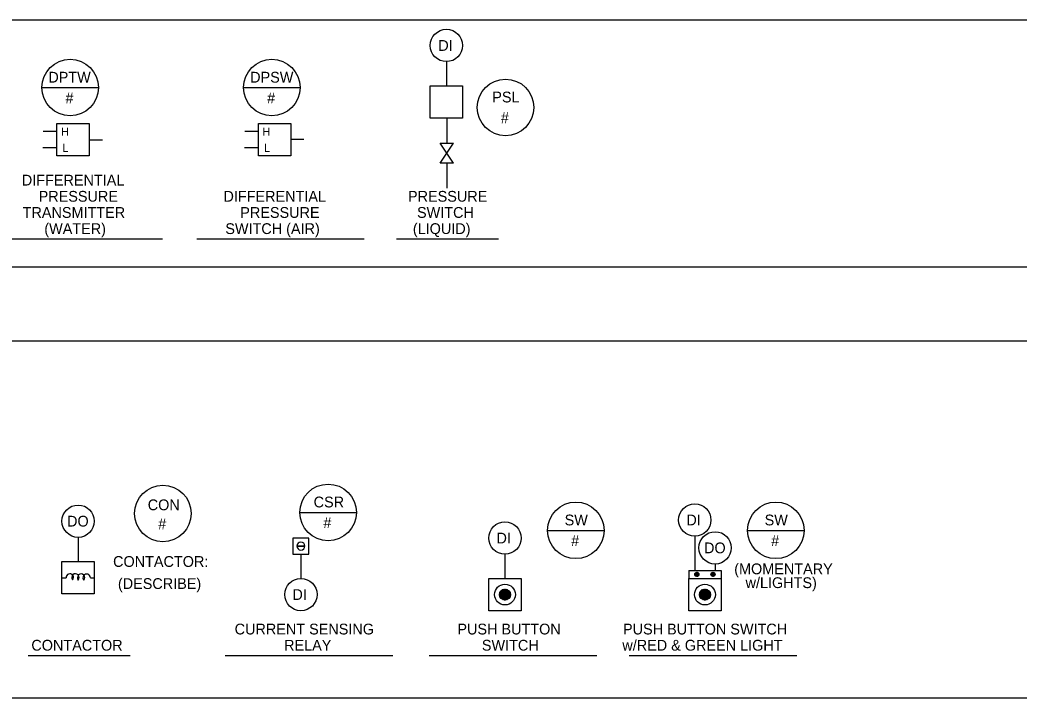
# Model space of a CAD drawing. Extents: x 10015 to 10283, y 10002 to 10184.
# Drawn here: x 10065.3 to 10127.1, y 10089.9 to 10131.8 of the extents above; entities that cross this region are included whole.
import ezdxf

# ---------------------------------------------------------------- set-up
doc = ezdxf.new("R2010")
doc.units = 0
for name, color, linetype in [('G-ANNO-TEXT', 7, 'Continuous'), ('G-DETL-LINE', 7, 'Continuous'), ('G-DETL-TEXT', 7, 'Continuous'), ('M-ANNO-NPLT', 7, 'Continuous')]:
    doc.layers.add(name, color=color, linetype=linetype)

msp = doc.modelspace()

# ---------------------------------------------------------------- linework, layer by layer
at = {"layer": 'G-ANNO-TEXT'}
for p, q in [((10063.729, 10118.291), (10074.097, 10118.291)), ((10076.201, 10118.291), (10086.569, 10118.291)), ((10088.558, 10118.291), (10094.87, 10118.291)), ((10065.778, 10092.522), (10072.09, 10092.522)), ((10077.965, 10092.522), (10088.333, 10092.522)), ((10090.586, 10092.522), (10100.955, 10092.522)), ((10102.957, 10092.522), (10113.325, 10092.522)), ((10102.957, 10092.522), (10113.325, 10092.522))]:
    msp.add_line(p, q, dxfattribs=at)
at = {"layer": 'G-DETL-LINE'}
for p, q in [((10091.647, 10129.256), (10091.647, 10127.76)), ((10090.647, 10127.76), (10092.647, 10127.76)), ((10090.647, 10125.76), (10090.647, 10127.76)), ((10092.647, 10127.76), (10092.647, 10125.76)), ((10067.561, 10123.427), (10067.561, 10125.427)), ((10067.561, 10125.427), (10069.561, 10125.427)), ((10069.561, 10125.427), (10069.561, 10123.427)), ((10080.033, 10123.427), (10080.033, 10125.427)), ((10080.033, 10125.427), (10082.033, 10125.427)), ((10082.033, 10125.427), (10082.033, 10123.427)), ((10092.647, 10125.76), (10090.647, 10125.76)), ((10091.672, 10125.775), (10091.672, 10124.213)), ((10067.561, 10124.927), (10066.714, 10124.927)), ((10080.033, 10124.927), (10079.186, 10124.927)), ((10069.561, 10124.427), (10070.377, 10124.427)), ((10082.012, 10124.464), (10082.827, 10124.464)), ((10091.261, 10122.977), (10092.084, 10124.213)), ((10091.261, 10124.213), (10092.084, 10124.213)), ((10092.084, 10122.977), (10091.261, 10124.213)), ((10067.561, 10123.927), (10066.684, 10123.927)), ((10080.033, 10123.927), (10079.156, 10123.927)), ((10069.561, 10123.427), (10067.561, 10123.427)), ((10082.033, 10123.427), (10080.033, 10123.427)), ((10092.084, 10122.977), (10091.261, 10122.977)), ((10091.672, 10122.992), (10091.672, 10121.43)), ((10068.867, 10099.83), (10068.867, 10098.334)), ((10083.147, 10099.789), (10082.147, 10099.789)), ((10082.147, 10099.789), (10082.147, 10098.789)), ((10083.147, 10098.789), (10083.147, 10099.789)), ((10107.012, 10099.903), (10107.012, 10097.789)), ((10082.147, 10098.789), (10083.147, 10098.789)), ((10082.647, 10099.289), (10082.397, 10099.289)), ((10082.397, 10099.289), (10082.647, 10099.289)), ((10082.897, 10099.289), (10082.647, 10099.289)), ((10082.647, 10099.289), (10082.897, 10099.289)), ((10082.647, 10098.789), (10082.647, 10097.289)), ((10095.269, 10098.786), (10095.269, 10097.289)), ((10067.867, 10098.334), (10069.867, 10098.334)), ((10067.867, 10096.334), (10067.867, 10098.334)), ((10069.867, 10098.334), (10069.867, 10096.334)), ((10108.266, 10098.178), (10108.266, 10097.789)), ((10106.639, 10097.789), (10106.639, 10097.289)), ((10107.013, 10097.537), (10107.142, 10097.666)), ((10107.013, 10097.537), (10107.142, 10097.666)), ((10107.013, 10097.549), (10107.149, 10097.413)), ((10107.013, 10097.549), (10107.149, 10097.413)), ((10107.013, 10097.526), (10107.127, 10097.413)), ((10107.013, 10097.526), (10107.127, 10097.413)), ((10107.014, 10097.517), (10107.162, 10097.664)), ((10107.014, 10097.561), (10107.118, 10097.664)), ((10107.014, 10097.517), (10107.162, 10097.664)), ((10107.014, 10097.561), (10107.118, 10097.664)), ((10107.016, 10097.568), (10107.168, 10097.416)), ((10107.016, 10097.568), (10107.168, 10097.416)), ((10107.019, 10097.499), (10107.18, 10097.66)), ((10107.019, 10097.499), (10107.18, 10097.66)), ((10107.021, 10097.585), (10107.185, 10097.421)), ((10107.021, 10097.585), (10107.185, 10097.421)), ((10107.024, 10097.593), (10107.086, 10097.654)), ((10107.024, 10097.593), (10107.086, 10097.654)), ((10107.025, 10097.484), (10107.195, 10097.653)), ((10107.025, 10097.484), (10107.195, 10097.653)), ((10107.028, 10097.6), (10107.2, 10097.428)), ((10107.028, 10097.6), (10107.2, 10097.428)), ((10107.033, 10097.469), (10107.209, 10097.645)), ((10107.033, 10097.469), (10107.209, 10097.645)), ((10107.036, 10097.614), (10107.214, 10097.436)), ((10107.036, 10097.614), (10107.214, 10097.436)), ((10107.043, 10097.457), (10107.222, 10097.636)), ((10107.043, 10097.457), (10107.222, 10097.636)), ((10107.046, 10097.626), (10107.226, 10097.446)), ((10107.046, 10097.626), (10107.226, 10097.446)), ((10107.054, 10097.446), (10107.233, 10097.625)), ((10107.054, 10097.446), (10107.233, 10097.625)), ((10107.058, 10097.636), (10107.237, 10097.457)), ((10107.058, 10097.636), (10107.237, 10097.457)), ((10107.066, 10097.436), (10107.243, 10097.613)), ((10107.066, 10097.436), (10107.243, 10097.613)), ((10107.07, 10097.646), (10107.246, 10097.47)), ((10107.07, 10097.646), (10107.246, 10097.47)), ((10107.08, 10097.427), (10107.252, 10097.599)), ((10107.08, 10097.427), (10107.252, 10097.599)), ((10107.085, 10097.654), (10107.254, 10097.484)), ((10107.085, 10097.654), (10107.254, 10097.484)), ((10107.095, 10097.42), (10107.258, 10097.584)), ((10107.095, 10097.42), (10107.258, 10097.584)), ((10107.1, 10097.66), (10107.26, 10097.5)), ((10107.1, 10097.66), (10107.26, 10097.5)), ((10107.112, 10097.415), (10107.263, 10097.567)), ((10107.112, 10097.415), (10107.263, 10097.567)), ((10107.118, 10097.664), (10107.265, 10097.518)), ((10107.118, 10097.664), (10107.265, 10097.518)), ((10107.131, 10097.413), (10107.266, 10097.548)), ((10107.131, 10097.413), (10107.266, 10097.548)), ((10107.138, 10097.666), (10107.266, 10097.538)), ((10107.138, 10097.666), (10107.266, 10097.538)), ((10107.154, 10097.413), (10107.266, 10097.525)), ((10107.154, 10097.413), (10107.266, 10097.525)), ((10107.163, 10097.664), (10107.264, 10097.562)), ((10107.163, 10097.664), (10107.264, 10097.562)), ((10107.196, 10097.653), (10107.253, 10097.595)), ((10107.196, 10097.653), (10107.253, 10097.595)), ((10108.141, 10097.666), (10108.012, 10097.538)), ((10108.141, 10097.666), (10108.012, 10097.538)), ((10108.148, 10097.413), (10108.013, 10097.548)), ((10108.148, 10097.413), (10108.013, 10097.548)), ((10108.125, 10097.413), (10108.013, 10097.525)), ((10108.125, 10097.413), (10108.013, 10097.525)), ((10108.161, 10097.664), (10108.014, 10097.518)), ((10108.161, 10097.664), (10108.014, 10097.518)), ((10108.116, 10097.664), (10108.015, 10097.562)), ((10108.116, 10097.664), (10108.015, 10097.562)), ((10108.167, 10097.415), (10108.016, 10097.567)), ((10108.167, 10097.415), (10108.016, 10097.567)), ((10108.179, 10097.66), (10108.019, 10097.5)), ((10108.179, 10097.66), (10108.019, 10097.5)), ((10108.184, 10097.42), (10108.021, 10097.584)), ((10108.184, 10097.42), (10108.021, 10097.584)), ((10108.194, 10097.654), (10108.025, 10097.484)), ((10108.194, 10097.654), (10108.025, 10097.484)), ((10108.083, 10097.653), (10108.026, 10097.595)), ((10108.083, 10097.653), (10108.026, 10097.595)), ((10108.199, 10097.427), (10108.027, 10097.599)), ((10108.199, 10097.427), (10108.027, 10097.599)), ((10108.209, 10097.646), (10108.033, 10097.47)), ((10108.209, 10097.646), (10108.033, 10097.47)), ((10108.213, 10097.436), (10108.036, 10097.613)), ((10108.213, 10097.436), (10108.036, 10097.613)), ((10108.221, 10097.636), (10108.042, 10097.457)), ((10108.221, 10097.636), (10108.042, 10097.457)), ((10108.225, 10097.446), (10108.046, 10097.625)), ((10108.225, 10097.446), (10108.046, 10097.625)), ((10108.233, 10097.626), (10108.053, 10097.446)), ((10108.233, 10097.626), (10108.053, 10097.446)), ((10108.236, 10097.457), (10108.057, 10097.636)), ((10108.236, 10097.457), (10108.057, 10097.636)), ((10108.243, 10097.614), (10108.065, 10097.436)), ((10108.243, 10097.614), (10108.065, 10097.436)), ((10108.246, 10097.469), (10108.07, 10097.645)), ((10108.246, 10097.469), (10108.07, 10097.645)), ((10108.251, 10097.6), (10108.079, 10097.428)), ((10108.251, 10097.6), (10108.079, 10097.428)), ((10108.254, 10097.484), (10108.084, 10097.653)), ((10108.254, 10097.484), (10108.084, 10097.653)), ((10108.258, 10097.585), (10108.094, 10097.421)), ((10108.258, 10097.585), (10108.094, 10097.421)), ((10108.26, 10097.499), (10108.099, 10097.66)), ((10108.26, 10097.499), (10108.099, 10097.66)), ((10108.263, 10097.568), (10108.111, 10097.416)), ((10108.263, 10097.568), (10108.111, 10097.416)), ((10108.264, 10097.517), (10108.117, 10097.664)), ((10108.264, 10097.517), (10108.117, 10097.664)), ((10108.266, 10097.549), (10108.13, 10097.413)), ((10108.266, 10097.549), (10108.13, 10097.413)), ((10108.266, 10097.537), (10108.137, 10097.666)), ((10108.266, 10097.537), (10108.137, 10097.666)), ((10108.266, 10097.526), (10108.152, 10097.413)), ((10108.266, 10097.526), (10108.152, 10097.413)), ((10108.265, 10097.561), (10108.161, 10097.664)), ((10108.265, 10097.561), (10108.161, 10097.664)), ((10108.255, 10097.593), (10108.193, 10097.654)), ((10108.255, 10097.593), (10108.193, 10097.654)), ((10067.867, 10097.334), (10068.032, 10097.334)), ((10068.032, 10097.334), (10068.127, 10097.334)), ((10069.627, 10097.331), (10069.867, 10097.331)), ((10094.269, 10097.289), (10096.269, 10097.289)), ((10094.269, 10095.289), (10094.269, 10097.289)), ((10096.269, 10097.289), (10096.269, 10095.289)), ((10106.639, 10097.289), (10108.639, 10097.289)), ((10106.639, 10095.289), (10106.639, 10097.289)), ((10106.639, 10097.289), (10108.639, 10097.289)), ((10106.639, 10095.289), (10106.639, 10097.289)), ((10107.019, 10097.498), (10107.098, 10097.419)), ((10107.019, 10097.498), (10107.098, 10097.419)), ((10107.183, 10097.42), (10107.259, 10097.496)), ((10107.183, 10097.42), (10107.259, 10097.496)), ((10108.096, 10097.42), (10108.02, 10097.496)), ((10108.096, 10097.42), (10108.02, 10097.496)), ((10108.26, 10097.498), (10108.181, 10097.419)), ((10108.26, 10097.498), (10108.181, 10097.419)), ((10108.639, 10097.289), (10108.639, 10095.289)), ((10108.639, 10097.289), (10108.639, 10095.289)), ((10069.867, 10096.334), (10067.867, 10096.334)), ((10094.93, 10096.283), (10095.275, 10096.628)), ((10094.931, 10096.314), (10095.294, 10095.952)), ((10094.935, 10096.347), (10095.212, 10096.623)), ((10094.936, 10096.229), (10095.329, 10096.623)), ((10094.939, 10096.366), (10095.345, 10095.959)), ((10094.948, 10096.182), (10095.376, 10096.611)), ((10094.953, 10096.411), (10095.39, 10095.973)), ((10094.962, 10096.433), (10095.126, 10096.596)), ((10094.965, 10096.141), (10095.418, 10096.594)), ((10094.971, 10096.451), (10095.431, 10095.992)), ((10094.986, 10096.103), (10095.455, 10096.572)), ((10094.994, 10096.487), (10095.467, 10096.014)), ((10095.011, 10096.069), (10095.489, 10096.547)), ((10095.021, 10096.52), (10095.499, 10096.041)), ((10095.04, 10096.039), (10095.519, 10096.518)), ((10095.051, 10096.548), (10095.528, 10096.071)), ((10095.073, 10096.013), (10095.545, 10096.485)), ((10095.085, 10096.573), (10095.553, 10096.105)), ((10095.109, 10095.991), (10095.568, 10096.449)), ((10095.122, 10096.595), (10095.574, 10096.143)), ((10095.15, 10095.972), (10095.586, 10096.408)), ((10095.165, 10096.611), (10095.591, 10096.185)), ((10095.195, 10095.959), (10095.6, 10096.363)), ((10095.212, 10096.623), (10095.603, 10096.232)), ((10095.247, 10095.951), (10095.607, 10096.311)), ((10095.266, 10096.628), (10095.608, 10096.286)), ((10095.33, 10096.622), (10095.602, 10096.351)), ((10095.419, 10096.593), (10095.573, 10096.439)), ((10107.301, 10096.283), (10107.646, 10096.628)), ((10107.301, 10096.283), (10107.646, 10096.628)), ((10107.302, 10096.314), (10107.665, 10095.952)), ((10107.302, 10096.314), (10107.665, 10095.952)), ((10107.306, 10096.229), (10107.699, 10096.623)), ((10107.306, 10096.347), (10107.582, 10096.623)), ((10107.306, 10096.229), (10107.699, 10096.623)), ((10107.306, 10096.347), (10107.582, 10096.623)), ((10107.31, 10096.366), (10107.716, 10095.959)), ((10107.31, 10096.366), (10107.716, 10095.959)), ((10107.318, 10096.182), (10107.746, 10096.611)), ((10107.318, 10096.182), (10107.746, 10096.611)), ((10107.323, 10096.411), (10107.761, 10095.973)), ((10107.323, 10096.411), (10107.761, 10095.973)), ((10107.333, 10096.433), (10107.496, 10096.596)), ((10107.333, 10096.433), (10107.496, 10096.596)), ((10107.335, 10096.141), (10107.788, 10096.594)), ((10107.335, 10096.141), (10107.788, 10096.594)), ((10107.342, 10096.451), (10107.801, 10095.992)), ((10107.342, 10096.451), (10107.801, 10095.992)), ((10107.357, 10096.103), (10107.826, 10096.572)), ((10107.357, 10096.103), (10107.826, 10096.572)), ((10107.365, 10096.487), (10107.837, 10096.014)), ((10107.365, 10096.487), (10107.837, 10096.014)), ((10107.382, 10096.069), (10107.859, 10096.547)), ((10107.382, 10096.069), (10107.859, 10096.547)), ((10107.391, 10096.52), (10107.87, 10096.041)), ((10107.391, 10096.52), (10107.87, 10096.041)), ((10107.411, 10096.039), (10107.889, 10096.518)), ((10107.411, 10096.039), (10107.889, 10096.518)), ((10107.421, 10096.548), (10107.899, 10096.071)), ((10107.421, 10096.548), (10107.899, 10096.071)), ((10107.443, 10096.013), (10107.916, 10096.485)), ((10107.443, 10096.013), (10107.916, 10096.485)), ((10107.455, 10096.573), (10107.924, 10096.105)), ((10107.455, 10096.573), (10107.924, 10096.105)), ((10107.48, 10095.991), (10107.938, 10096.449)), ((10107.48, 10095.991), (10107.938, 10096.449)), ((10107.493, 10096.595), (10107.945, 10096.143)), ((10107.493, 10096.595), (10107.945, 10096.143)), ((10107.52, 10095.972), (10107.957, 10096.408)), ((10107.52, 10095.972), (10107.957, 10096.408)), ((10107.535, 10096.611), (10107.962, 10096.185)), ((10107.535, 10096.611), (10107.962, 10096.185)), ((10107.566, 10095.959), (10107.97, 10096.363)), ((10107.566, 10095.959), (10107.97, 10096.363)), ((10107.582, 10096.623), (10107.973, 10096.232)), ((10107.582, 10096.623), (10107.973, 10096.232)), ((10107.617, 10095.951), (10107.977, 10096.311)), ((10107.617, 10095.951), (10107.977, 10096.311)), ((10107.636, 10096.628), (10107.978, 10096.286)), ((10107.636, 10096.628), (10107.978, 10096.286)), ((10107.701, 10096.622), (10107.973, 10096.351)), ((10107.701, 10096.622), (10107.973, 10096.351)), ((10107.789, 10096.593), (10107.943, 10096.439)), ((10107.789, 10096.593), (10107.943, 10096.439)), ((10094.932, 10096.255), (10095.234, 10095.952)), ((10094.949, 10096.179), (10095.159, 10095.969)), ((10095.307, 10095.953), (10095.606, 10096.251)), ((10095.384, 10095.971), (10095.588, 10096.174)), ((10107.303, 10096.255), (10107.605, 10095.952)), ((10107.303, 10096.255), (10107.605, 10095.952)), ((10107.319, 10096.179), (10107.529, 10095.969)), ((10107.319, 10096.179), (10107.529, 10095.969)), ((10107.678, 10095.953), (10107.976, 10096.251)), ((10107.678, 10095.953), (10107.976, 10096.251)), ((10107.755, 10095.971), (10107.958, 10096.174)), ((10107.755, 10095.971), (10107.958, 10096.174)), ((10096.269, 10095.289), (10094.269, 10095.289)), ((10108.639, 10095.289), (10106.639, 10095.289)), ((10108.639, 10095.289), (10106.639, 10095.289))]:
    msp.add_line(p, q, dxfattribs=at)
for points in [[(10015.495, 10131.834), (10130.67, 10131.834), (10130.67, 10116.546), (10015.495, 10116.546)], [(10015.495, 10111.994), (10130.67, 10111.994), (10130.67, 10089.891), (10015.495, 10089.891)]]:
    msp.add_lwpolyline(points, close=True, dxfattribs=at)
msp.add_lwpolyline([(10106.639, 10097.789), (10108.639, 10097.789), (10108.639, 10097.289)], dxfattribs=at)
for centre, radius in [((10091.647, 10130.256), 1), ((10107.012, 10100.903), 1), ((10107.012, 10100.903), 1), ((10068.867, 10100.83), 1), ((10095.269, 10099.786), 1), ((10108.266, 10099.178), 1), ((10108.266, 10099.178), 1), ((10107.139, 10097.539), 0.127), ((10107.139, 10097.539), 0.127), ((10108.139, 10097.539), 0.127), ((10108.139, 10097.539), 0.127), ((10082.648, 10096.289), 1), ((10095.269, 10096.289), 0.643), ((10107.639, 10096.289), 0.643), ((10107.639, 10096.289), 0.643), ((10095.269, 10096.289), 0.339), ((10107.639, 10096.289), 0.339), ((10107.639, 10096.289), 0.339)]:
    msp.add_circle(centre, radius, dxfattribs=at)
for centre, radius, start, end in [((10082.647, 10099.289), 0.25, 0, 180), ((10082.647, 10099.289), 0.25, 180, 0), ((10068.354, 10097.348), 0.227, 319.70097, 183.55311), ((10068.705, 10097.349), 0.231, 316.67887, 219.97644), ((10069.05, 10097.339), 0.231, 316.67887, 219.97644), ((10069.396, 10097.329), 0.231, 0.54142, 219.97644)]:
    msp.add_arc(centre, radius, start, end, dxfattribs=at)
at = {"layer": 'G-DETL-TEXT'}
for centre in [(10068.377, 10127.651), (10080.849, 10127.651), (10095.304, 10126.425), (10084.329, 10101.374), (10074.113, 10101.307), (10099.652, 10100.263), (10112.023, 10100.263), (10112.023, 10100.263)]:
    msp.add_circle(centre, 1.75, dxfattribs=at)
at = {"layer": 'M-ANNO-NPLT'}
for p, q in [((10066.627, 10127.651), (10070.127, 10127.651)), ((10079.099, 10127.651), (10082.599, 10127.651)), ((10082.579, 10101.374), (10086.079, 10101.374)), ((10097.902, 10100.263), (10101.402, 10100.263)), ((10110.273, 10100.263), (10113.773, 10100.263)), ((10110.273, 10100.263), (10113.773, 10100.263))]:
    msp.add_line(p, q, dxfattribs=at)

# ---------------------------------------------------------------- texts
at = {"layer": 'G-ANNO-TEXT'}
for s, height, p in [('DIFFERENTIAL', 0.66667, (10065.388, 10121.593)), ('PRESSURE', 0.6667, (10066.427, 10120.593)), ('DIFFERENTIAL', 0.66667, (10077.859, 10120.593)), ('PRESSURE', 0.6667, (10089.273, 10120.593)), ('TRANSMITTER', 0.66667, (10065.438, 10119.593)), ('PRESSURE', 0.6667, (10078.899, 10119.593)), ('SWITCH', 0.6667, (10089.83, 10119.593)), ('(WATER)', 0.6667, (10066.777, 10118.593)), ('SWITCH (AIR)', 0.66667, (10077.972, 10118.593)), ('(LIQUID)', 0.6667, (10089.572, 10118.593)), ('CURRENT SENSING', 0.66667, (10078.55, 10093.823)), ('PUSH BUTTON', 0.66667, (10092.328, 10093.823)), ('PUSH BUTTON SWITCH', 0.66667, (10102.571, 10093.823)), ('CONTACTOR', 0.6667, (10065.976, 10092.823)), ('RELAY', 0.6667, (10081.609, 10092.823)), ('SWITCH', 0.6667, (10093.842, 10092.823)), ('w/RED & GREEN LIGHT', 0.66667, (10102.53, 10092.823))]:
    msp.add_text(s, height=height, dxfattribs=at).set_placement(p)
at = {"layer": 'G-DETL-LINE'}
for s, height, p in [('DI', 0.6667, (10091.145, 10129.923)), ('H', 0.5, (10067.806, 10124.677)), ('H', 0.5, (10080.277, 10124.677)), ('L', 0.5, (10067.891, 10123.677)), ('L', 0.5, (10080.362, 10123.677)), ('DI', 0.6667, (10106.489, 10100.57)), ('DI', 0.6667, (10106.489, 10100.57)), ('DO', 0.6667, (10068.184, 10100.497)), ('DI', 0.6667, (10094.746, 10099.452)), ('DO', 0.6667, (10107.583, 10098.845)), ('CONTACTOR:', 0.6667, (10071.03, 10098.003)), ('(MOMENTARY', 0.6667, (10109.45, 10097.548)), ('(DESCRIBE)', 0.6667, (10071.33, 10096.637)), ('w/LIGHTS)', 0.6667, (10110.151, 10096.692)), ('DI', 0.6667, (10082.124, 10095.956))]:
    msp.add_text(s, height=height, dxfattribs=at).set_placement(p)
at = {"layer": 'G-DETL-TEXT'}
for s, height, p in [('DPTW', 0.6667, (10067.025, 10127.96)), ('DPSW', 0.6667, (10079.509, 10127.96)), ('#', 0.667, (10068.087, 10126.676)), ('#', 0.667, (10080.558, 10126.676)), ('PSL', 0.6667, (10094.486, 10126.734)), ('#', 0.667, (10095.014, 10125.45)), ('CON', 0.6667, (10073.173, 10101.508)), ('CSR', 0.6667, (10083.435, 10101.683)), ('SW', 0.6667, (10098.96, 10100.571)), ('SW', 0.6667, (10111.33, 10100.571)), ('SW', 0.6667, (10111.33, 10100.571)), ('#', 0.667, (10073.823, 10100.332)), ('#', 0.667, (10084.038, 10100.398)), ('#', 0.667, (10099.362, 10099.287)), ('#', 0.667, (10111.733, 10099.287))]:
    msp.add_text(s, height=height, dxfattribs=at).set_placement(p)

doc.saveas('drawing.dxf')
